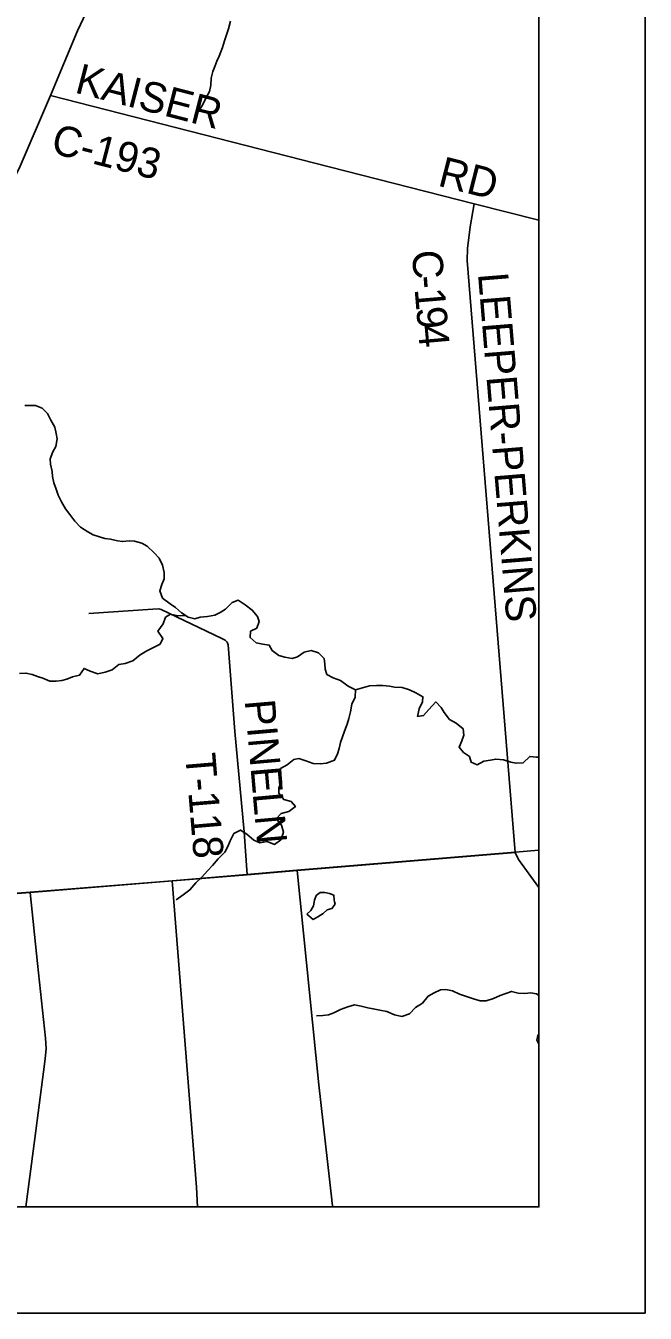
# Model space of a CAD drawing. Extents: x 0 to 34, y 0 to 22.
# Drawn here: x 8.418 to 9, y 14 to 15.21 of the extents above; entities that cross this region are included whole.
import ezdxf

# ---------------------------------------------------------------- set-up
doc = ezdxf.new("R2010")
doc.units = 0
for name, color, linetype in [('GM_X_Corporation', 7, 'Continuous'), ('GM_X_County_Road', 7, 'Continuous'), ('GM_X_County_Road_Text', 7, 'Continuous'), ('GM_X_Minor_Lake', 7, 'Continuous'), ('GM_X_Minor_River', 7, 'Continuous'), ('GM_X_State_Route', 7, 'Continuous'), ('GM_X_Township_Road', 7, 'Continuous'), ('GM_X_Township_Road_Text', 7, 'Continuous'), ('SH_Data', 7, 'Continuous')]:
    doc.layers.add(name, color=color, linetype=linetype)

msp = doc.modelspace()

# ---------------------------------------------------------------- linework, layer by layer
at = {"layer": 'GM_X_Corporation'}
for points in [[(2.7052, 14.1), (8.9, 14.1), (8.9, 20.9), (3.3687, 20.9)], [(8.0146, 17.4385), (8.0061, 17.4015), (7.9483, 17.1186), (7.8667, 16.7439), (7.8171, 16.5163), (7.6624, 15.7725), (7.761, 15.7513), (7.7853, 15.4515), (7.8145, 15.0705), (8.0549, 15.0964), (8.0668, 14.9397), (8.0887, 14.5411), (8.0986, 14.3711), (8.2117, 14.3797), (8.4217, 14.3956), (8.5553, 14.4065), (8.6255, 14.4123), (8.6725, 14.4163), (8.8777, 14.4334), (8.8814, 14.4337), (8.9, 14.4352), (8.9, 17.4353)]]:
    msp.add_lwpolyline(points, dxfattribs=at)
for points in [[(8.579, 14.1), (8.9, 14.1), (8.9, 14.4352), (8.8814, 14.4337), (8.8777, 14.4334), (8.6725, 14.4163), (8.6255, 14.4123), (8.5553, 14.4065), (8.5781, 14.1185)], [(5.0367, 14.1), (8.579, 14.1), (8.5781, 14.1185), (8.5553, 14.4065), (8.4217, 14.3956), (8.2117, 14.3797), (8.0986, 14.3711), (7.9912, 14.363), (7.8543, 14.3535), (7.661, 14.3447), (7.5929, 14.3405), (7.4631, 14.3291), (7.1407, 14.2995), (6.5134, 14.2426), (6.0344, 14.1984), (5.9982, 14.195), (5.4229, 14.1455), (5.0357, 14.1114)]]:
    msp.add_lwpolyline(points, close=True, dxfattribs=at)
at = {"layer": 'GM_X_County_Road'}
for p, q in [((8.6726, 14.4161), (8.8778, 14.4331)), ((8.5559, 14.4063), (8.6256, 14.412)), ((8.6256, 14.412), (8.6726, 14.4161))]:
    msp.add_line(p, q, dxfattribs=at)
for points in [[(8.4409, 15.1443), (8.7027, 15.0774), (8.839, 15.0427), (8.9, 15.0272)], [(8.839, 15.0427), (8.8355, 15.021), (8.8328, 15.0006), (8.8327, 14.9892), (8.8778, 14.4331)], [(8.8778, 14.4331), (8.8809, 14.4264), (8.9, 14.4001)], [(7.9913, 14.3627), (8.0987, 14.3709), (8.2118, 14.3794), (8.4218, 14.3953), (8.5554, 14.4063), (8.5559, 14.4063)]]:
    msp.add_lwpolyline(points, dxfattribs=at)
at = {"layer": 'GM_X_Minor_Lake'}
for points in [[(8.708, 14.3865), (8.7075, 14.3886), (8.7072, 14.393), (8.703, 14.3945), (8.6987, 14.3955), (8.6943, 14.3955), (8.6905, 14.3925), (8.6892, 14.3883), (8.6882, 14.383), (8.6855, 14.3786), (8.6817, 14.3749)], [(8.6817, 14.3749), (8.6878, 14.3701), (8.6923, 14.3724), (8.6971, 14.3756), (8.7011, 14.379), (8.7054, 14.3805), (8.7085, 14.3843), (8.708, 14.3865)], [(8.9, 14.2623), (8.8991, 14.261), (8.8981, 14.2567), (8.8998, 14.2529), (8.9, 14.2529)]]:
    msp.add_lwpolyline(points, dxfattribs=at)
at = {"layer": 'GM_X_Minor_River'}
for points in [[(8.6101, 15.2142), (8.6082, 15.207), (8.6067, 15.2022), (8.6045, 15.1958), (8.6026, 15.1895), (8.5994, 15.1814), (8.5973, 15.1766), (8.5954, 15.1715), (8.5936, 15.1668), (8.5919, 15.1607), (8.5915, 15.1541), (8.5902, 15.148), (8.5867, 15.1412), (8.5837, 15.1353), (8.5797, 15.1289)], [(8.6003, 14.6585), (8.5954, 14.656), (8.5884, 14.6547), (8.5815, 14.654), (8.5766, 14.6527), (8.5704, 14.654), (8.5639, 14.6582), (8.5584, 14.6632), (8.5535, 14.6668), (8.5463, 14.6721), (8.5435, 14.679), (8.5454, 14.6849), (8.5476, 14.6902), (8.5478, 14.6962), (8.5463, 14.7031), (8.5429, 14.7095), (8.5384, 14.7147), (8.5316, 14.7208), (8.5266, 14.7238), (8.5198, 14.7256), (8.5151, 14.7258), (8.5084, 14.7252), (8.5037, 14.726), (8.4973, 14.7273), (8.492, 14.7281), (8.4868, 14.7297), (8.481, 14.7314), (8.4759, 14.7342), (8.4689, 14.7388), (8.4636, 14.7442), (8.4589, 14.7506), (8.4549, 14.7558), (8.4511, 14.7624), (8.4481, 14.7687), (8.4461, 14.7744), (8.444, 14.7805), (8.4427, 14.7862), (8.4425, 14.7911), (8.4407, 14.798), (8.4405, 14.8029), (8.4432, 14.8095), (8.4458, 14.8144), (8.447, 14.8217), (8.4463, 14.8268), (8.4448, 14.8327), (8.4412, 14.8393), (8.438, 14.8456), (8.4329, 14.8506), (8.4266, 14.8532), (8.4168, 14.8529)], [(8.9, 14.5226), (8.8976, 14.5227), (8.8914, 14.5233), (8.8851, 14.5174), (8.8785, 14.5169), (8.8735, 14.5179), (8.8667, 14.52), (8.8595, 14.5208), (8.8546, 14.5198), (8.8483, 14.5187), (8.8421, 14.5155), (8.8362, 14.5178), (8.8347, 14.5231), (8.8292, 14.5271), (8.8249, 14.5321), (8.8274, 14.5378), (8.8293, 14.5433), (8.8287, 14.5493), (8.8223, 14.5545), (8.8161, 14.5579), (8.8108, 14.5644), (8.8081, 14.5693), (8.8032, 14.5745), (8.7966, 14.5675), (8.7916, 14.5616), (8.7859, 14.5609), (8.7873, 14.5681), (8.7907, 14.5745), (8.7909, 14.5793), (8.7843, 14.5831), (8.7784, 14.5857), (8.7716, 14.588), (8.7642, 14.5885), (8.7595, 14.5892), (8.7532, 14.59), (8.7474, 14.5898), (8.7407, 14.5897), (8.7341, 14.5876), (8.7276, 14.5859), (8.7208, 14.5894), (8.7136, 14.5947), (8.7066, 14.5972), (8.7006, 14.6004), (8.6991, 14.6052), (8.6989, 14.6101), (8.698, 14.6154), (8.6927, 14.6206), (8.6859, 14.6227), (8.6794, 14.6212), (8.673, 14.6169), (8.6682, 14.6153), (8.6612, 14.6165), (8.6555, 14.6182), (8.6491, 14.6228), (8.6465, 14.6279), (8.6404, 14.6289), (8.6342, 14.6301), (8.6285, 14.635), (8.6289, 14.6409), (8.6348, 14.6439), (8.6369, 14.6502), (8.6356, 14.6549), (8.6305, 14.6608), (8.624, 14.6658), (8.6174, 14.67), (8.6115, 14.6679), (8.6053, 14.6617), (8.6003, 14.6585)], [(8.5676, 14.6558), (8.5607, 14.6554), (8.5537, 14.6571), (8.5489, 14.6541), (8.5468, 14.648), (8.5419, 14.641), (8.5464, 14.6342), (8.5441, 14.6289), (8.5376, 14.6255), (8.5314, 14.6226), (8.5251, 14.6187), (8.5181, 14.613), (8.511, 14.6106), (8.505, 14.6095), (8.4987, 14.6047), (8.4923, 14.6023), (8.4854, 14.601), (8.4782, 14.6035), (8.4724, 14.606), (8.4682, 14.5997), (8.4615, 14.598), (8.4562, 14.596), (8.4515, 14.5946), (8.4462, 14.5939), (8.4401, 14.5941), (8.4337, 14.5968), (8.4287, 14.5983), (8.4236, 14.6001), (8.4177, 14.6016), (8.4117, 14.6012)], [(8.7277, 14.5859), (8.7272, 14.5791), (8.7242, 14.5723), (8.723, 14.5653), (8.7213, 14.5588), (8.7197, 14.5537), (8.7174, 14.5469), (8.7155, 14.5417), (8.7136, 14.5364), (8.7121, 14.5307), (8.7107, 14.5256), (8.7079, 14.5196), (8.7003, 14.5169), (8.6944, 14.5164), (8.6879, 14.5166), (8.6809, 14.5191), (8.6743, 14.5212), (8.6696, 14.5205), (8.6635, 14.5155), (8.6572, 14.5118), (8.6574, 14.5059), (8.6581, 14.4992), (8.6554, 14.4939), (8.6556, 14.4886), (8.6601, 14.4827), (8.6671, 14.481), (8.6711, 14.4762), (8.6648, 14.4715), (8.6578, 14.4696), (8.6531, 14.4645), (8.658, 14.4586), (8.6598, 14.4522), (8.6575, 14.445), (8.6513, 14.4406), (8.6444, 14.4433), (8.6376, 14.442), (8.6319, 14.4445), (8.6255, 14.4502), (8.6196, 14.454), (8.6132, 14.4508), (8.6099, 14.4438), (8.6075, 14.4385), (8.6046, 14.4332), (8.5985, 14.427), (8.593, 14.4207), (8.5884, 14.4158), (8.5831, 14.4099), (8.5776, 14.4046), (8.5719, 14.3978), (8.5656, 14.3933), (8.5591, 14.3884)], [(8.9, 14.2987), (8.8977, 14.3001), (8.8924, 14.3011), (8.8869, 14.3006), (8.8805, 14.3008), (8.8744, 14.3025), (8.8689, 14.3006), (8.8636, 14.2985), (8.8573, 14.2959), (8.8505, 14.2937), (8.8448, 14.2935), (8.8386, 14.2954), (8.8319, 14.2977), (8.8253, 14.2998), (8.8187, 14.3029), (8.8124, 14.3042), (8.8075, 14.3039), (8.8014, 14.3012), (8.7959, 14.298), (8.7906, 14.2914), (8.7841, 14.2872), (8.7782, 14.2814), (8.771, 14.2789), (8.7644, 14.2805), (8.7572, 14.2835), (8.7506, 14.2847), (8.7441, 14.286), (8.7392, 14.287), (8.7329, 14.2887), (8.7267, 14.2897), (8.7204, 14.288), (8.7136, 14.2854), (8.7071, 14.2822), (8.7022, 14.2803), (8.6969, 14.2799), (8.6908, 14.2796)]]:
    msp.add_lwpolyline(points, dxfattribs=at)
at = {"layer": 'GM_X_State_Route'}
msp.add_lwpolyline([(7.9913, 14.3627), (8.0888, 14.5408), (8.2059, 14.7535), (8.247, 14.8278), (8.2621, 14.8528), (8.2768, 14.8754), (8.3341, 14.9613), (8.3972, 15.05), (8.4039, 15.0612), (8.4115, 15.0757), (8.4409, 15.1443), (8.4662, 15.2052), (8.4824, 15.2399), (8.5465, 15.3683), (8.8663, 15.9455), (8.9, 16.0063)], dxfattribs=at)
at = {"layer": 'GM_X_Township_Road'}
for p, q in [((8.5371, 14.6618), (8.4769, 14.6575)), ((8.6726, 14.4161), (8.6256, 14.412))]:
    msp.add_line(p, q, dxfattribs=at)
for points in [[(8.6256, 14.412), (8.6228, 14.4525), (8.6143, 14.5466), (8.6079, 14.628), (8.607, 14.6306), (8.6051, 14.6325), (8.6018, 14.634), (8.545, 14.6614), (8.5426, 14.6621), (8.5371, 14.6618)], [(8.7054, 14.1067), (8.6932, 14.2145), (8.6726, 14.4161)], [(8.4178, 14.1), (8.4261, 14.1641), (8.4342, 14.2268), (8.4359, 14.2392), (8.4367, 14.2489), (8.4362, 14.2585), (8.4286, 14.3288), (8.4218, 14.3953)], [(8.7062, 14.1), (8.7058, 14.1032), (8.7054, 14.1067)]]:
    msp.add_lwpolyline(points, dxfattribs=at)
at = {"layer": 'SH_Data'}
for p, q in [((9, 21), (9, 14)), ((8.9, 20.9), (8.9, 14.1)), ((2.1, 14.1), (8.9, 14.1)), ((2, 14), (9, 14))]:
    msp.add_line(p, q, dxfattribs=at)

# ---------------------------------------------------------------- texts
at = {"layer": 'GM_X_County_Road_Text'}
for s, height, rotation, p in [('KAISER', 0.02841, 345.5474, (8.4627, 15.1473)), ('C-193', 0.02841, 345.5645, (8.4401, 15.0907)), ('RD', 0.02841, 345.7266, (8.804, 15.0598)), ('C', 0.0284, 272.823, (8.7809, 14.9986)), ('-', 0.0284, 274.5199, (8.7821, 14.9744)), ('LEEPER-PERKINS', 0.028409, 274.7079, (8.8427, 14.9769)), ('1', 0.0284, 274.8639, (8.7831, 14.9626)), ('9', 0.0284, 274.9916, (8.7846, 14.945)), ('4', 0.0284, 275.0311, (8.7861, 14.9276))]:
    msp.add_text(s, height=height, rotation=rotation, dxfattribs=at).set_placement(p)
at = {"layer": 'GM_X_Township_Road_Text'}
for s, rotation, p in [('PINE', 274.9694, (8.6234, 14.5758)), ('T-118', 274.7865, (8.5674, 14.5253)), ('LN', 275.149, (8.6309, 14.4883))]:
    msp.add_text(s, height=0.02841, rotation=rotation, dxfattribs=at).set_placement(p)

doc.saveas('drawing.dxf')
